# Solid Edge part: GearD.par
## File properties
Author: Chalangana Oshan
Template: iso metric part.par
Last saved by: Nimesh.N
Revision: 29
Application: Solid Edge
Density: 7250.000 kg/m^3
Accuracy: 0.990
Username: Nimesh.N
Material: Iron:0.6025 , EN-GJL-250
Face Style: Gray
Fill Style: ANSI31(Iron)
Grouping: Iron\Gray Cast Iron
LibraryName: Materials-DIN
Coef. of Thermal Exp: 1.05e-05
Thermal Conductivity: 58.0
Specific Heat: 460.0
Modulus of Elasticity: 120000003072.0
Poisson's Ratio: 0.26
Yield Stress: 165593984.0
Ultimate Stress: 250000000.0
Elongation: 0.0
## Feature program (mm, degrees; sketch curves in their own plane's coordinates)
sketch for "unnamed Protrusion 1" plane through (0, 0, 0) normal (0, 0, 1) x-axis (1, 0, 0)
  circle centre (0, 0) radius 135
extrude "unnamed Protrusion 1" add finite 130 along -normal
sketch used by "unnamed Cutout 1" plane through (0, 0, 0) normal (0, 0, 1) x-axis (1, 0, 0)
  line (0, 0) -> (-16.92, 133.9355)
  line (0, 0) -> (-14.1113, 134.2605)
  line (0, 0) -> (-23.4425, 132.949)
  line (-3.5337, 112.4445) -> (3.5337, 112.4445)
  arc centre (-61.6978, 97.7155) radius 60 from (-14.1113, 134.2605) to (-3.5337, 112.4445) cw
  arc centre (61.6978, 97.7155) radius 60 from (14.1113, 134.2605) to (3.5337, 112.4445) ccw
extrude "unnamed Cutout 1" cut through along -normal
pattern "unnamed Pattern 1" of "unnamed Cutout 1"
pattern "unnamed Pattern 2"
sketch for "ExtrudedProtrusion_2" plane through (0, -0.3698, 0) normal (0, 0, 1) x-axis (0.535827, 0.844328, 0)
extrude "ExtrudedProtrusion_2" add finite 18 along +normal
sketch for "unnamed Cutout 2" plane through (0, 0, 18) normal (0, 0, 1) x-axis (0, 1, 0)
extrude "unnamed Cutout 2" cut through along -normal
sketch for "unnamed Cutout 3" plane through (0, 0, 18) normal (0, 0, 1) x-axis (0, 1, 0)
extrude "unnamed Cutout 3" cut through along -normal
Other named dimensions: "ExtrudedSurface_3": FiniteDepth = 130 mm
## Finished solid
Body 1: sheet body, 1 face, 2 edges, 0 vertices.
  Faces by surface: cylinder 1
  Edges by curve: circle 2
Body 2: solid body, 106 faces, 312 edges, 208 vertices.
  Faces by surface: cylinder 76, plane 30
  Edges by curve: line 160, circle 152
Bounding box of the edges (mm): 269.763 x 269.260 x 130.000, from (-134.8816, -135, -130) to (134.8816, 134.2605, 0).
Cylindrical faces by radius (mm): R35 x1, R60 x50, R125 x1, R135 x25
Planar faces by outward normal: +x 1, +y 2, +z 1, -y 1, -z 1, oblique 24
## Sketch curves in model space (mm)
line (0, 0, 0) -> (-23.4425, 132.949, 0)
line (0, 0, 0) -> (-16.92, 133.9355, 0)
line (0, 0, 0) -> (4.2405, 134.9334, 0)
line (0, 0, 0) -> (-4.2405, 134.9334, 0)
arc centre (61.6978, 97.7155, 0) radius 60 from (14.1113, 134.2605, 0) through (7.7091, 123.8923, 0) to (3.5337, 112.4445, 0)
line (-3.5337, 112.4445, 0) -> (3.5337, 112.4445, 0)
arc centre (-61.6978, 97.7155, 0) radius 60 from (-14.1113, 134.2605, 0) through (-7.7091, 123.8923, 0) to (-3.5337, 112.4445, 0)
line (0, 0, 0) -> (-14.1113, 134.2605, 0)
circle centre (0, 0, 0) radius 135
circle centre (0, 0, 0) radius 125
circle centre (0, 0, 0) radius 112.5
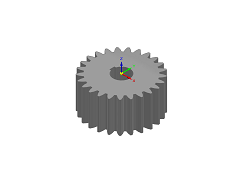
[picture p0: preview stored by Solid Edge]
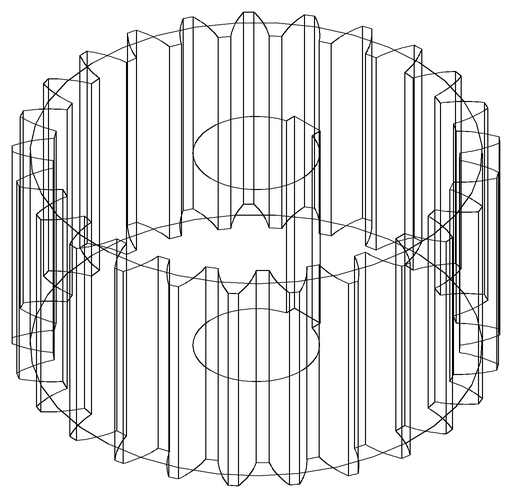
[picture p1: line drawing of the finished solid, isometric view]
